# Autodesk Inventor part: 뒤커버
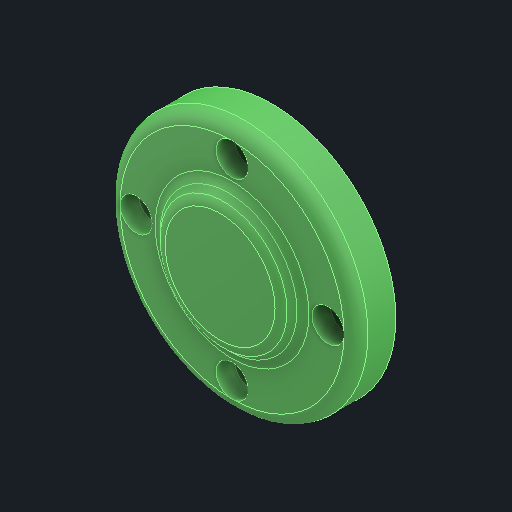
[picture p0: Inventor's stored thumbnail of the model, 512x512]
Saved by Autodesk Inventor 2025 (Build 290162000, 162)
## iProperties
Created: 2025-08
Part Number: 뒤커버
Material: 알루미늄 6061
Document SubType Name: Modeling
Designer: infra006
Density: 2.71 g/cm^3
Appearance: 기본값
Author: jhkim
Sending System: Autodesk Inventor 2026
Preprocessor: ST-DEVELOPER v20.1
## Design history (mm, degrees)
feature "솔리드1"
node "솔리드2"
